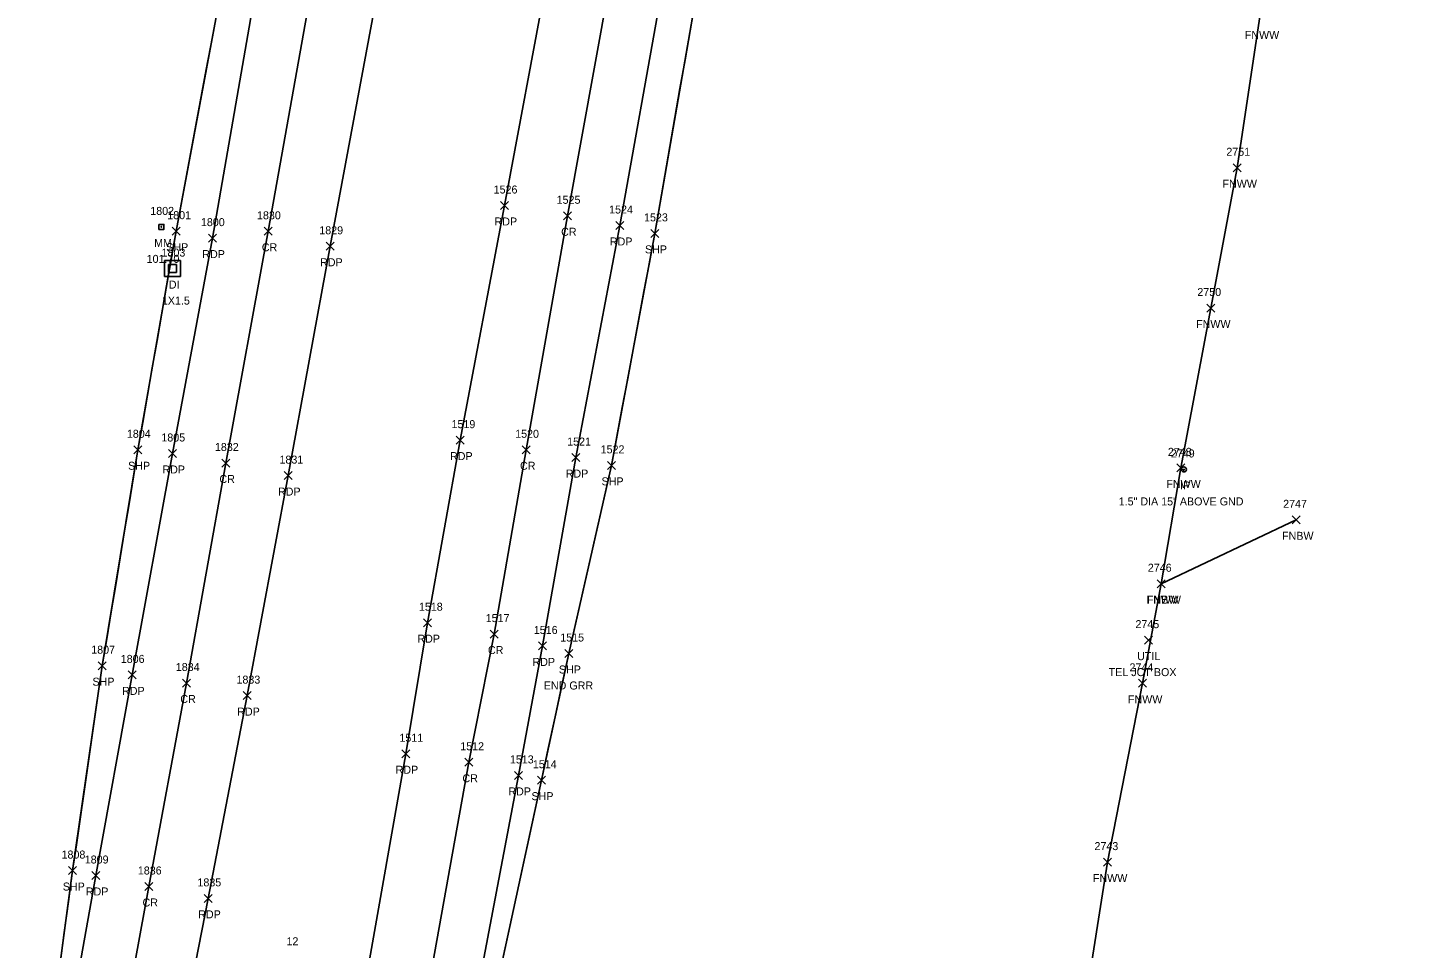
# Model space of a CAD drawing. Extents: x 1472022 to 1479249, y 777216 to 786527.
# Drawn here: x 1473646.9 to 1473992, y 779884.8 to 780115.1 of the extents above; entities that cross this region are included whole.
import ezdxf

# ---------------------------------------------------------------- set-up
doc = ezdxf.new("R2010")
doc.units = 0
for name, color, linetype in [('C_I', 7, 'Continuous'), ('D_A', 7, 'Continuous'), ('D_C', 7, 'Continuous'), ('D_I', 7, 'Continuous'), ('DS', 7, 'Continuous'), ('L_A', 7, 'Continuous'), ('L_I', 7, 'Continuous'), ('L_TIC', 7, 'Continuous'), ('LFNC', 7, 'Continuous'), ('LSOGP', 7, 'Continuous'), ('M_A', 7, 'Continuous'), ('M_C', 7, 'Continuous'), ('M_I', 7, 'Continuous'), ('MPIR', 7, 'Continuous'), ('P_A', 7, 'Continuous'), ('P_C', 7, 'Continuous'), ('P_I', 7, 'Continuous'), ('P_TIC', 7, 'Continuous'), ('PET', 7, 'Continuous'), ('PRC', 7, 'Continuous'), ('PSP', 7, 'Continuous'), ('S_A', 7, 'Continuous'), ('S_C', 7, 'Continuous'), ('S_I', 7, 'Continuous'), ('SRM', 7, 'Continuous'), ('U_A', 7, 'Continuous'), ('U_C', 7, 'Continuous'), ('U_I', 7, 'Continuous'), ('UDEFAULT', 7, 'Continuous')]:
    doc.layers.add(name, color=color, linetype=linetype)

msp = doc.modelspace()

# ---------------------------------------------------------------- linework, layer by layer
at = {"layer": 'DS'}
for p, q in [((1473681.13, 780056.86), (1473685.13, 780056.86)), ((1473681.13, 780052.86), (1473681.13, 780056.86)), ((1473682.13, 780053.86), (1473682.13, 780055.86)), ((1473682.13, 780055.86), (1473684.13, 780055.86)), ((1473684.13, 780055.86), (1473684.13, 780053.86)), ((1473685.13, 780056.86), (1473685.13, 780052.86)), ((1473685.13, 780052.86), (1473681.13, 780052.86)), ((1473684.13, 780053.86), (1473682.13, 780053.86)), ((1473683.14, 780054.86), (1473683.14, 780054.86)), ((1473683.14, 780054.86), (1473683.14, 780054.86))]:
    msp.add_line(p, q, dxfattribs=at)
at = {"layer": 'L_TIC'}
for points in [[(1473948.23, 780079.08), (1473950.23, 780081.08)], [(1473950.23, 780079.08), (1473948.23, 780081.08)], [(1473941.64, 780044), (1473943.64, 780046)], [(1473943.64, 780044), (1473941.64, 780046)], [(1473934.19, 780004.03), (1473936.19, 780006.03)], [(1473936.19, 780004.03), (1473934.19, 780006.03)], [(1473963, 779991.03), (1473965, 779993.03)], [(1473965, 779991.03), (1473963, 779993.03)], [(1473929.24, 779975.05), (1473931.24, 779977.05)], [(1473931.24, 779975.05), (1473929.24, 779977.05)], [(1473929.24, 779975.05), (1473931.24, 779977.05)], [(1473931.24, 779975.05), (1473929.24, 779977.05)], [(1473924.6, 779950.14), (1473926.6, 779952.14)], [(1473926.6, 779950.14), (1473924.6, 779952.14)], [(1473915.84, 779905.43), (1473917.84, 779907.43)], [(1473917.84, 779905.43), (1473915.84, 779907.43)]]:
    msp.add_lwpolyline(points, dxfattribs=at)
at = {"layer": 'LFNC'}
for points in [[(1473875, 779673.99), (1473881.89, 779709.03), (1473887.76, 779743.71), (1473891.94, 779764.72), (1473898.61, 779803.9), (1473906.31, 779845.37), (1473911.16, 779870.48), (1473916.84, 779906.43), (1473925.6, 779951.14), (1473930.24, 779976.05), (1473935.19, 780005.03), (1473942.64, 780045), (1473949.23, 780080.08), (1473954.8, 780117.32), (1473965.64, 780175.79), (1473975.53, 780227.06), (1473985.2, 780275.69), (1474013.15, 780426.76), (1474027.53, 780457.02), (1474055.53, 780518.26), (1474067.56, 780545.19), (1474081.74, 780575.7)], [(1473930.24, 779976.05), (1473964, 779992.03)]]:
    msp.add_lwpolyline(points, dxfattribs=at)
at = {"layer": 'LSOGP'}
for points in [[(1473694.6, 780120.88), (1473693.09, 780112.79), (1473691.57, 780104.69), (1473690.06, 780096.6), (1473688.55, 780088.5), (1473687.03, 780080.41), (1473685.52, 780072.32), (1473684.01, 780064.22), (1473682.82, 780057.39), (1473681.63, 780050.56), (1473680.44, 780043.72), (1473679.25, 780036.89), (1473678.05, 780030.05), (1473676.86, 780023.22), (1473675.67, 780016.39), (1473674.48, 780009.55), (1473673.37, 780002.8), (1473672.25, 779996.05), (1473671.14, 779989.3), (1473670.03, 779982.55), (1473668.91, 779975.8), (1473667.8, 779969.05), (1473666.69, 779962.3), (1473665.57, 779955.55), (1473664.64, 779949.15), (1473663.72, 779942.75), (1473662.79, 779936.34), (1473661.86, 779929.94), (1473660.93, 779923.53), (1473660.01, 779917.13), (1473659.08, 779910.72), (1473658.15, 779904.32), (1473657.11, 779896.58), (1473656.07, 779888.85), (1473655.03, 779881.11)], [(1473765.86, 779883.03), (1473767.44, 779890.35), (1473769.01, 779897.66), (1473770.59, 779904.98), (1473772.16, 779912.29), (1473773.74, 779919.61), (1473775.32, 779926.92), (1473777.03, 779934.84), (1473778.74, 779942.76), (1473780.45, 779950.68), (1473782.16, 779958.6), (1473783.5, 779964.49), (1473784.83, 779970.37), (1473786.16, 779976.25), (1473787.5, 779982.13), (1473788.83, 779988.01), (1473790.16, 779993.89), (1473791.5, 779999.77), (1473792.83, 780005.65), (1473794.19, 780012.9), (1473795.54, 780020.16), (1473796.9, 780027.41), (1473798.25, 780034.66), (1473799.61, 780041.91), (1473800.97, 780049.16), (1473802.32, 780056.41), (1473803.68, 780063.67), (1473804.94, 780070.91), (1473806.2, 780078.15), (1473807.45, 780085.39), (1473808.71, 780092.63), (1473809.97, 780099.87), (1473811.23, 780107.11), (1473812.49, 780114.35), (1473813.75, 780121.6)]]:
    msp.add_lwpolyline(points, dxfattribs=at)
at = {"layer": 'MPIR'}
for radius in [0.625, 0.0833]:
    msp.add_circle((1473935.95, 780004.63), radius, dxfattribs=at)
at = {"layer": 'P_TIC'}
for points in [[(1473765.14, 780069.64), (1473767.14, 780071.64)], [(1473767.14, 780069.64), (1473765.14, 780071.64)], [(1473780.83, 780067.07), (1473782.83, 780069.07)], [(1473782.83, 780067.07), (1473780.83, 780069.07)], [(1473793.95, 780064.64), (1473795.95, 780066.64)], [(1473795.95, 780064.64), (1473793.95, 780066.64)], [(1473683.01, 780063.22), (1473685.01, 780065.22)], [(1473685.01, 780063.22), (1473683.01, 780065.22)], [(1473692.08, 780061.48), (1473694.08, 780063.48)], [(1473694.08, 780061.48), (1473692.08, 780063.48)], [(1473706.02, 780063.19), (1473708.02, 780065.19)], [(1473708.02, 780063.19), (1473706.02, 780065.19)], [(1473802.68, 780062.67), (1473804.68, 780064.67)], [(1473804.68, 780062.67), (1473802.68, 780064.67)], [(1473721.51, 780059.44), (1473723.51, 780061.44)], [(1473723.51, 780059.44), (1473721.51, 780061.44)], [(1473673.48, 780008.55), (1473675.48, 780010.55)], [(1473675.48, 780008.55), (1473673.48, 780010.55)], [(1473754, 780010.96), (1473756, 780012.96)], [(1473756, 780010.96), (1473754, 780012.96)], [(1473770.55, 780008.55), (1473772.55, 780010.55)], [(1473772.55, 780008.55), (1473770.55, 780010.55)], [(1473682.1, 780007.62), (1473684.1, 780009.62)], [(1473684.1, 780007.62), (1473682.1, 780009.62)], [(1473695.41, 780005.24), (1473697.41, 780007.24)], [(1473697.41, 780005.24), (1473695.41, 780007.24)], [(1473782.9, 780006.6), (1473784.9, 780008.6)], [(1473784.9, 780006.6), (1473782.9, 780008.6)], [(1473791.83, 780004.65), (1473793.83, 780006.65)], [(1473793.83, 780004.65), (1473791.83, 780006.65)], [(1473710.99, 780002.09), (1473712.99, 780004.09)], [(1473712.99, 780002.09), (1473710.99, 780004.09)], [(1473745.83, 779965.3), (1473747.83, 779967.3)], [(1473747.83, 779965.3), (1473745.83, 779967.3)], [(1473762.53, 779962.46), (1473764.53, 779964.46)], [(1473764.53, 779962.46), (1473762.53, 779964.46)], [(1473774.61, 779959.49), (1473776.61, 779961.49)], [(1473776.61, 779959.49), (1473774.61, 779961.49)], [(1473781.16, 779957.6), (1473783.16, 779959.6)], [(1473783.16, 779957.6), (1473781.16, 779959.6)], [(1473664.57, 779954.55), (1473666.57, 779956.55)], [(1473666.57, 779954.55), (1473664.57, 779956.55)], [(1473672.01, 779952.25), (1473674.01, 779954.25)], [(1473674.01, 779952.25), (1473672.01, 779954.25)], [(1473685.64, 779950.22), (1473687.64, 779952.22)], [(1473687.64, 779950.22), (1473685.64, 779952.22)], [(1473700.81, 779947.07), (1473702.81, 779949.07)], [(1473702.81, 779947.07), (1473700.81, 779949.07)], [(1473740.4, 779932.53), (1473742.4, 779934.53)], [(1473742.4, 779932.53), (1473740.4, 779934.53)], [(1473756.16, 779930.4), (1473758.16, 779932.4)], [(1473758.16, 779930.4), (1473756.16, 779932.4)], [(1473768.57, 779927.11), (1473770.57, 779929.11)], [(1473770.57, 779927.11), (1473768.57, 779929.11)], [(1473774.32, 779925.92), (1473776.32, 779927.92)], [(1473776.32, 779925.92), (1473774.32, 779927.92)], [(1473657.15, 779903.32), (1473659.15, 779905.32)], [(1473659.15, 779903.32), (1473657.15, 779905.32)], [(1473662.96, 779902.08), (1473664.96, 779904.08)], [(1473664.96, 779902.08), (1473662.96, 779904.08)], [(1473676.2, 779899.33), (1473678.2, 779901.33)], [(1473678.2, 779899.33), (1473676.2, 779901.33)], [(1473691.05, 779896.36), (1473693.05, 779898.36)], [(1473693.05, 779896.36), (1473691.05, 779898.36)]]:
    msp.add_lwpolyline(points, dxfattribs=at)
at = {"layer": 'PET'}
for points in [[(1473746.48, 779804.23), (1473735, 779806.45), (1473719.43, 779809.21), (1473722.68, 779826.96), (1473722.64, 779829.09), (1473731.65, 779877.71), (1473741.4, 779933.53), (1473746.83, 779966.3), (1473755, 780011.96), (1473766.14, 780070.64), (1473776.66, 780127.43), (1473786.78, 780182.03), (1473796.49, 780236.66), (1473805.8, 780286.73), (1473813.14, 780328.66), (1473818.03, 780354.99), (1473826.83, 780403.57), (1473832.05, 780432.32), (1473842.07, 780489.82), (1473851.78, 780539.26), (1473858.97, 780579.12), (1473867.36, 780624.13)], [(1473748.73, 779803.86), (1473746.48, 779804.23), (1473749.84, 779823.79), (1473758.54, 779869.63), (1473769.57, 779928.11), (1473775.61, 779960.49), (1473783.9, 780007.6), (1473794.95, 780065.64), (1473805.21, 780123.07), (1473815.24, 780176.97), (1473825.12, 780231.74), (1473834.38, 780281.06), (1473842, 780323.35), (1473851.32, 780373.06), (1473861.15, 780428.07), (1473871.31, 780483.08), (1473880.48, 780535.96), (1473887.71, 780574.3), (1473895.6, 780618.75)], [(1473794.13, 780615.24), (1473782.52, 780552.37), (1473771.2, 780492.12), (1473760.19, 780429.94), (1473749.17, 780369.33), (1473737.05, 780303.75), (1473725.28, 780241.43), (1473714.85, 780182.67), (1473704.33, 780127.35), (1473693.08, 780062.48), (1473683.1, 780008.62), (1473673.01, 779953.25), (1473663.96, 779903.08), (1473652.83, 779841.01), (1473649.09, 779823)], [(1473823.42, 780612.39), (1473811.33, 780545.89), (1473800.44, 780487.51), (1473789.09, 780424.89), (1473785.11, 780403.28), (1473778.08, 780362.23), (1473770.89, 780328.95), (1473766.97, 780298.8), (1473754.95, 780235.54), (1473743.53, 780174.64), (1473733.79, 780120.94), (1473722.51, 780060.44), (1473711.99, 780003.09), (1473701.81, 779948.07), (1473692.05, 779897.36), (1473680.21, 779836.9), (1473679.29, 779834.87), (1473676.24, 779818.18), (1473663.54, 779820.45), (1473649.09, 779823)]]:
    msp.add_lwpolyline(points, dxfattribs=at)
at = {"layer": 'PRC'}
for points in [[(1473735, 779806.45), (1473738.41, 779825.86), (1473746.88, 779873.78), (1473757.16, 779931.4), (1473763.53, 779963.46), (1473771.55, 780009.55), (1473781.83, 780068.07), (1473792.3, 780125.59), (1473802.3, 780178.66), (1473811.81, 780233.39), (1473821.47, 780283.6), (1473828.72, 780325.68), (1473837.7, 780374.01), (1473847.63, 780429.6), (1473858, 780486.03), (1473867.42, 780537.6), (1473874.56, 780576.61), (1473882.64, 780621.02)], [(1473807.59, 780614.57), (1473795.53, 780548.63), (1473784.81, 780489.97), (1473773.42, 780426.81), (1473762.25, 780366.77), (1473750.55, 780303.15), (1473738.69, 780240.19), (1473727.91, 780180.81), (1473717.59, 780123.6), (1473707.02, 780064.19), (1473696.41, 780006.24), (1473686.64, 779951.22), (1473677.2, 779900.33), (1473668.24, 779851.14), (1473663.54, 779820.45)]]:
    msp.add_lwpolyline(points, dxfattribs=at)
at = {"layer": 'PSP'}
for points in [[(1473748.73, 779803.86), (1473752.42, 779823.56), (1473762.71, 779868.4), (1473775.32, 779926.92), (1473782.16, 779958.6), (1473792.83, 780005.65), (1473803.68, 780063.67), (1473813.75, 780121.6), (1473823.74, 780173.97), (1473833.9, 780230.35), (1473842.97, 780280.28), (1473850.64, 780321.91), (1473860.15, 780373.2), (1473869.95, 780426.63), (1473880.31, 780480.63), (1473890.06, 780534.18), (1473897.21, 780573.03), (1473905.39, 780617.74)], [(1473785.49, 780617.45), (1473774.09, 780553.9), (1473763.03, 780493.85), (1473751.84, 780432.12), (1473740.58, 780370.87), (1473727.95, 780303.67), (1473717.24, 780242.77), (1473706.31, 780183.74), (1473696.11, 780128.97), (1473684.01, 780064.22), (1473674.48, 780009.55), (1473665.57, 779955.55), (1473658.15, 779904.32), (1473649.83, 779842.42), (1473650, 779841.1), (1473646.9, 779823.47)]]:
    msp.add_lwpolyline(points, dxfattribs=at)
at = {"layer": 'SRM'}
msp.add_lwpolyline([(1473679.7, 780065.91), (1473680.95, 780065.91), (1473680.95, 780064.66), (1473679.7, 780064.66)], close=True, dxfattribs=at)
msp.add_circle((1473680.33, 780065.29), 0.0833, dxfattribs=at)
at = {"layer": 'UDEFAULT'}
for points in [[(1473926.08, 779960.94), (1473928.08, 779962.94)], [(1473928.08, 779960.94), (1473926.08, 779962.94)]]:
    msp.add_lwpolyline(points, dxfattribs=at)

# ---------------------------------------------------------------- texts
at = {"layer": 'C_I'}
msp.add_text('12', height=2, dxfattribs=at).set_placement((1473711.61, 779885.63))
at = {"layer": 'D_A'}
msp.add_text('DI', height=2, dxfattribs=at).set_placement((1473682.19, 780049.86))
at = {"layer": 'D_C'}
msp.add_text('1X1.5', height=2, dxfattribs=at).set_placement((1473680.46, 780045.86))
at = {"layer": 'D_I'}
msp.add_text('1803', height=2, dxfattribs=at).set_placement((1473680.37, 780057.86))
at = {"layer": 'L_A'}
for s, p in [('FNWW', (1473951.15, 780112.32)), ('FNWW', (1473945.58, 780075.08)), ('FNWW', (1473938.98, 780040)), ('FNWW', (1473931.54, 780000.03)), ('FNBW', (1473960.47, 779987.03)), ('FNWW', (1473926.59, 779971.05)), ('FNBW', (1473926.71, 779971.05)), ('FNWW', (1473921.94, 779946.14)), ('FNWW', (1473913.19, 779901.43))]:
    msp.add_text(s, height=2, dxfattribs=at).set_placement(p)
at = {"layer": 'L_I'}
for s, p in [('2751', (1473946.54, 780083.08)), ('2750', (1473939.29, 780048)), ('2748', (1473931.93, 780008.03)), ('2747', (1473960.74, 779995.03)), ('2746', (1473926.92, 779979.05)), ('2746', (1473926.92, 779979.05)), ('2744', (1473922.34, 779954.14)), ('2743', (1473913.58, 779909.43))]:
    msp.add_text(s, height=2, dxfattribs=at).set_placement(p)
at = {"layer": 'M_A'}
msp.add_text('IP', height=2, dxfattribs=at).set_placement((1473935, 779999.63))
at = {"layer": 'M_C'}
msp.add_text('1.5" DIA 15" ABOVE GND', height=2, dxfattribs=at).set_placement((1473919.64, 779995.63))
at = {"layer": 'M_I'}
msp.add_text('2749', height=2, dxfattribs=at).set_placement((1473932.68, 780007.63))
at = {"layer": 'P_A'}
for s, p in [('RDP', (1473763.62, 780065.64)), ('CR', (1473780.27, 780063.07)), ('RDP', (1473792.44, 780060.64)), ('SHP', (1473681.54, 780059.22)), ('RDP', (1473690.56, 780057.48)), ('CR', (1473705.45, 780059.19)), ('SHP', (1473801.22, 780058.67)), ('RDP', (1473720, 780055.44)), ('RDP', (1473752.48, 780006.96)), ('SHP', (1473672.02, 780004.55)), ('RDP', (1473680.59, 780003.62)), ('CR', (1473694.85, 780001.24)), ('CR', (1473769.98, 780004.55)), ('RDP', (1473781.39, 780002.6)), ('RDP', (1473709.48, 779998.09)), ('SHP', (1473790.36, 780000.65)), ('RDP', (1473744.32, 779961.3)), ('CR', (1473761.97, 779958.46)), ('RDP', (1473773.1, 779955.49)), ('SHP', (1473779.7, 779953.6)), ('SHP', (1473663.11, 779950.55)), ('RDP', (1473670.5, 779948.25)), ('CR', (1473685.07, 779946.22)), ('RDP', (1473699.29, 779943.07)), ('RDP', (1473738.88, 779928.53)), ('CR', (1473755.6, 779926.4)), ('RDP', (1473767.06, 779923.11)), ('SHP', (1473772.85, 779921.92)), ('SHP', (1473655.69, 779899.32)), ('RDP', (1473661.45, 779898.08)), ('CR', (1473675.63, 779895.33)), ('RDP', (1473689.54, 779892.36))]:
    msp.add_text(s, height=2, dxfattribs=at).set_placement(p)
at = {"layer": 'P_C'}
msp.add_text('END GRR', height=2, dxfattribs=at).set_placement((1473775.92, 779949.6))
at = {"layer": 'P_I'}
for s, p in [('1526', (1473763.39, 780073.64)), ('1525', (1473779.14, 780071.07)), ('1801', (1473681.8, 780067.22)), ('1830', (1473704.24, 780067.19)), ('1524', (1473792.26, 780068.64)), ('1800', (1473690.22, 780065.48)), ('1829', (1473719.81, 780063.44)), ('1523', (1473800.99, 780066.67)), ('1804', (1473671.71, 780012.55)), ('1805', (1473680.33, 780011.62)), ('1519', (1473752.86, 780014.96)), ('1520', (1473768.77, 780012.55)), ('1832', (1473693.72, 780009.24)), ('1521', (1473781.77, 780010.6)), ('1522', (1473790.14, 780008.65)), ('1831', (1473709.86, 780006.09)), ('1518', (1473744.71, 779969.3)), ('1517', (1473761.41, 779966.46)), ('1516', (1473773.43, 779963.49)), ('1515', (1473780.04, 779961.6)), ('1807', (1473662.8, 779958.55)), ('1806', (1473670.18, 779956.25)), ('1834', (1473683.94, 779954.22)), ('1833', (1473699.11, 779951.07)), ('1511', (1473739.84, 779936.53)), ('1512', (1473755.04, 779934.4)), ('1513', (1473767.45, 779931.11)), ('1514', (1473773.19, 779929.92)), ('1808', (1473655.38, 779907.32)), ('1809', (1473661.18, 779906.08)), ('1836', (1473674.45, 779903.33)), ('1835', (1473689.35, 779900.36))]:
    msp.add_text(s, height=2, dxfattribs=at).set_placement(p)
at = {"layer": 'S_A'}
msp.add_text('MM', height=2, dxfattribs=at).set_placement((1473678.52, 780060.29))
at = {"layer": 'S_C'}
msp.add_text('101.70', height=2, dxfattribs=at).set_placement((1473676.65, 780056.29))
at = {"layer": 'S_I'}
msp.add_text('1802', height=2, dxfattribs=at).set_placement((1473677.56, 780068.29))
at = {"layer": 'U_A'}
msp.add_text('UTIL', height=2, dxfattribs=at).set_placement((1473924.24, 779956.94))
at = {"layer": 'U_C'}
msp.add_text('TEL JCT BOX', height=2, dxfattribs=at).set_placement((1473917.14, 779952.94))
at = {"layer": 'U_I'}
msp.add_text('2745', height=2, dxfattribs=at).set_placement((1473923.82, 779964.94))

doc.saveas('drawing.dxf')
